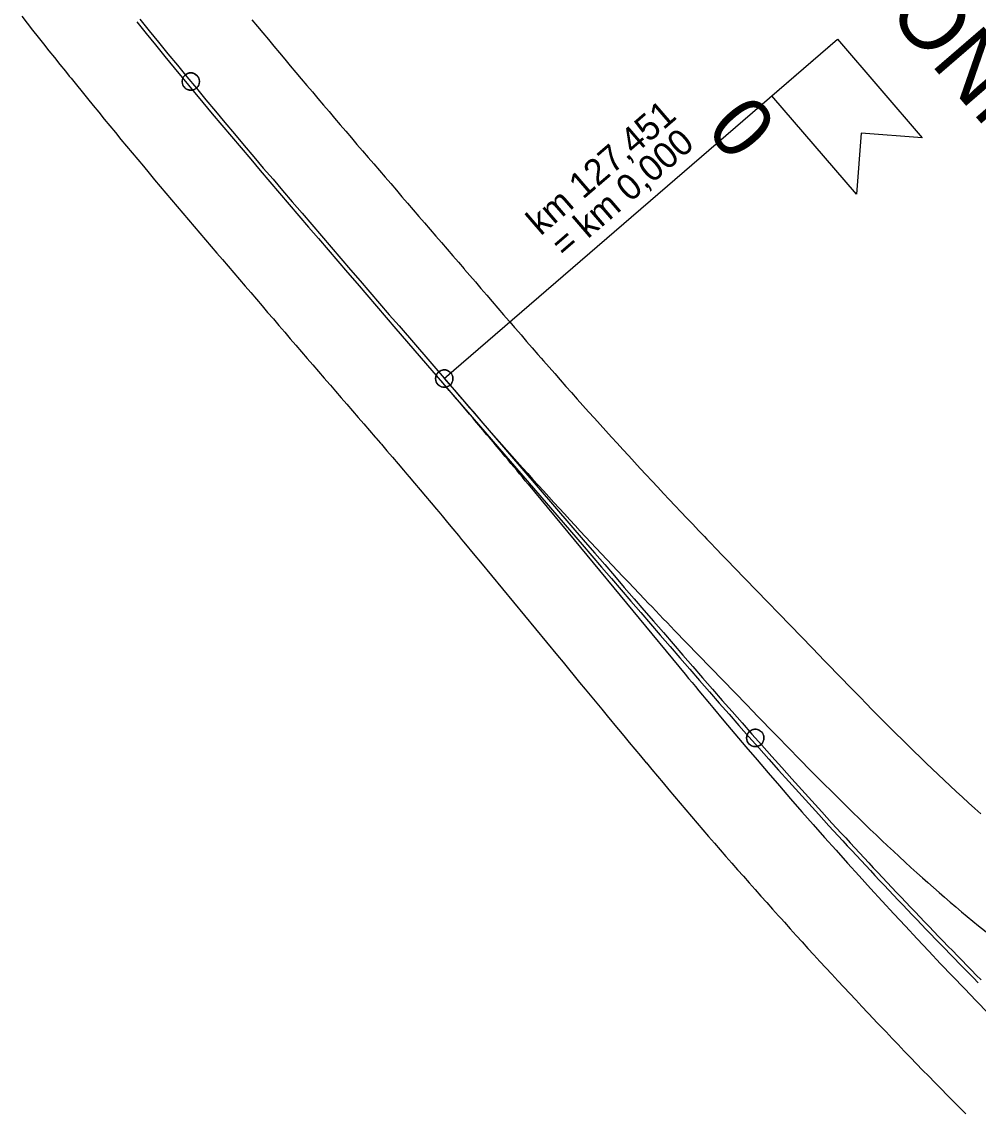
# Model space of a CAD drawing. Extents: x -670810 to -649614, y -1131928 to -1115069.
# Drawn here: x -669291 to -668186, y -1123186 to -1121929 of the extents above; entities that cross this region are included whole.
import ezdxf

# ---------------------------------------------------------------- set-up
doc = ezdxf.new("R2010")
doc.units = 0
for name, color, linetype in [('519 Var SK-4 Praporky stanic', 7, 'Continuous'), ('hranice_VRT_ZUR_Vysocina', 7, 'Continuous'), ('Situace - Osa koleje 2D', 7, 'Continuous'), ('Staničení - hlavní staničení + kolečka 1k', 7, 'Continuous')]:
    doc.layers.add(name, color=color, linetype=linetype)

# ---------------------------------------------------------------- blocks, each defined once
blk = doc.blocks.new('Sit10Kruh_104')
at = {"layer": 'Staničení - hlavní staničení + kolečka 1k'}
blk.add_lwpolyline([(10, 0), (10, 0.6), (9.9, 1.3), (9.8, 1.9), (9.7, 2.5), (9.5, 3.1), (9.3, 3.7), (9, 4.3), (8.8, 4.8), (8.4, 5.4), (8.1, 5.9), (7.7, 6.4), (7.3, 6.8), (6.8, 7.3), (6.4, 7.7), (5.9, 8.1), (5.4, 8.4), (4.8, 8.8), (4.3, 9), (3.7, 9.3), (3.1, 9.5), (2.5, 9.7), (1.9, 9.8), (1.3, 9.9), (0.6, 10), (0, 10), (-0.6, 10), (-1.3, 9.9), (-1.9, 9.8), (-2.5, 9.7), (-3.1, 9.5), (-3.7, 9.3), (-4.3, 9), (-4.8, 8.8), (-5.4, 8.4), (-5.9, 8.1), (-6.4, 7.7), (-6.8, 7.3), (-7.3, 6.8), (-7.7, 6.4), (-8.1, 5.9), (-8.4, 5.4), (-8.8, 4.8), (-9, 4.3), (-9.3, 3.7), (-9.5, 3.1), (-9.7, 2.5), (-9.8, 1.9), (-9.9, 1.3), (-10, 0.6), (-10, 0), (-10, -0.6), (-9.9, -1.3), (-9.8, -1.9), (-9.7, -2.5), (-9.5, -3.1), (-9.3, -3.7), (-9, -4.3), (-8.8, -4.8), (-8.4, -5.4), (-8.1, -5.9), (-7.7, -6.4), (-7.3, -6.8), (-6.8, -7.3), (-6.4, -7.7), (-5.9, -8.1), (-5.4, -8.4), (-4.8, -8.8), (-4.3, -9), (-3.7, -9.3), (-3.1, -9.5), (-2.5, -9.7), (-1.9, -9.8), (-1.3, -9.9), (-0.6, -10), (0, -10), (0.6, -10), (1.3, -9.9), (1.9, -9.8), (2.5, -9.7), (3.1, -9.5), (3.7, -9.3), (4.3, -9), (4.8, -8.8), (5.4, -8.4), (5.9, -8.1), (6.4, -7.7), (6.8, -7.3), (7.3, -6.8), (7.7, -6.4), (8.1, -5.9), (8.4, -5.4), (8.8, -4.8), (9, -4.3), (9.3, -3.7), (9.5, -3.1), (9.7, -2.5), (9.8, -1.9), (9.9, -1.3)], close=True, dxfattribs=at)
blk.add_circle((0, 0), 10, dxfattribs=at)
blk = doc.blocks.new('Sit10Kruh_105')
at = {"layer": 'Staničení - hlavní staničení + kolečka 1k'}
blk.add_lwpolyline([(10, 0), (10, 0.6), (9.9, 1.3), (9.8, 1.9), (9.7, 2.5), (9.5, 3.1), (9.3, 3.7), (9, 4.3), (8.8, 4.8), (8.4, 5.4), (8.1, 5.9), (7.7, 6.4), (7.3, 6.8), (6.8, 7.3), (6.4, 7.7), (5.9, 8.1), (5.4, 8.4), (4.8, 8.8), (4.3, 9), (3.7, 9.3), (3.1, 9.5), (2.5, 9.7), (1.9, 9.8), (1.3, 9.9), (0.6, 10), (0, 10), (-0.6, 10), (-1.3, 9.9), (-1.9, 9.8), (-2.5, 9.7), (-3.1, 9.5), (-3.7, 9.3), (-4.3, 9), (-4.8, 8.8), (-5.4, 8.4), (-5.9, 8.1), (-6.4, 7.7), (-6.8, 7.3), (-7.3, 6.8), (-7.7, 6.4), (-8.1, 5.9), (-8.4, 5.4), (-8.8, 4.8), (-9, 4.3), (-9.3, 3.7), (-9.5, 3.1), (-9.7, 2.5), (-9.8, 1.9), (-9.9, 1.3), (-10, 0.6), (-10, 0), (-10, -0.6), (-9.9, -1.3), (-9.8, -1.9), (-9.7, -2.5), (-9.5, -3.1), (-9.3, -3.7), (-9, -4.3), (-8.8, -4.8), (-8.4, -5.4), (-8.1, -5.9), (-7.7, -6.4), (-7.3, -6.8), (-6.8, -7.3), (-6.4, -7.7), (-5.9, -8.1), (-5.4, -8.4), (-4.8, -8.8), (-4.3, -9), (-3.7, -9.3), (-3.1, -9.5), (-2.5, -9.7), (-1.9, -9.8), (-1.3, -9.9), (-0.6, -10), (0, -10), (0.6, -10), (1.3, -9.9), (1.9, -9.8), (2.5, -9.7), (3.1, -9.5), (3.7, -9.3), (4.3, -9), (4.8, -8.8), (5.4, -8.4), (5.9, -8.1), (6.4, -7.7), (6.8, -7.3), (7.3, -6.8), (7.7, -6.4), (8.1, -5.9), (8.4, -5.4), (8.8, -4.8), (9, -4.3), (9.3, -3.7), (9.5, -3.1), (9.7, -2.5), (9.8, -1.9), (9.9, -1.3)], close=True, dxfattribs=at)
blk.add_circle((0, 0), 10, dxfattribs=at)
blk = doc.blocks.new('Sit10Kruh_167')
at = {"layer": 'Staničení - hlavní staničení + kolečka 1k'}
blk.add_lwpolyline([(10, 0), (10, 0.6), (9.9, 1.3), (9.8, 1.9), (9.7, 2.5), (9.5, 3.1), (9.3, 3.7), (9, 4.3), (8.8, 4.8), (8.4, 5.4), (8.1, 5.9), (7.7, 6.4), (7.3, 6.8), (6.8, 7.3), (6.4, 7.7), (5.9, 8.1), (5.4, 8.4), (4.8, 8.8), (4.3, 9), (3.7, 9.3), (3.1, 9.5), (2.5, 9.7), (1.9, 9.8), (1.3, 9.9), (0.6, 10), (0, 10), (-0.6, 10), (-1.3, 9.9), (-1.9, 9.8), (-2.5, 9.7), (-3.1, 9.5), (-3.7, 9.3), (-4.3, 9), (-4.8, 8.8), (-5.4, 8.4), (-5.9, 8.1), (-6.4, 7.7), (-6.8, 7.3), (-7.3, 6.8), (-7.7, 6.4), (-8.1, 5.9), (-8.4, 5.4), (-8.8, 4.8), (-9, 4.3), (-9.3, 3.7), (-9.5, 3.1), (-9.7, 2.5), (-9.8, 1.9), (-9.9, 1.3), (-10, 0.6), (-10, 0), (-10, -0.6), (-9.9, -1.3), (-9.8, -1.9), (-9.7, -2.5), (-9.5, -3.1), (-9.3, -3.7), (-9, -4.3), (-8.8, -4.8), (-8.4, -5.4), (-8.1, -5.9), (-7.7, -6.4), (-7.3, -6.8), (-6.8, -7.3), (-6.4, -7.7), (-5.9, -8.1), (-5.4, -8.4), (-4.8, -8.8), (-4.3, -9), (-3.7, -9.3), (-3.1, -9.5), (-2.5, -9.7), (-1.9, -9.8), (-1.3, -9.9), (-0.6, -10), (0, -10), (0.6, -10), (1.3, -9.9), (1.9, -9.8), (2.5, -9.7), (3.1, -9.5), (3.7, -9.3), (4.3, -9), (4.8, -8.8), (5.4, -8.4), (5.9, -8.1), (6.4, -7.7), (6.8, -7.3), (7.3, -6.8), (7.7, -6.4), (8.1, -5.9), (8.4, -5.4), (8.8, -4.8), (9, -4.3), (9.3, -3.7), (9.5, -3.1), (9.7, -2.5), (9.8, -1.9), (9.9, -1.3)], close=True, dxfattribs=at)
blk.add_circle((0, 0), 10, dxfattribs=at)
blk = doc.blocks.new('_U497')
at = {"layer": '519 Var SK-4 Praporky stanic'}
blk.add_line((-45.8, -299.9), (-45.8, 299.9), dxfattribs=at)
blk.add_lwpolyline([(-45.8, 299.9), (104.2, 299.9), (54.2, 249.9), (104.2, 199.9), (-45.8, 199.9)], close=True, dxfattribs=at)
for s, p in [('km 127,451', (-97.4, -108.5)), ('= km 0,000', (-59.2, -104))]:
    blk.add_text(s, height=30, rotation=90, dxfattribs=at).set_placement(p)
blk = doc.blocks.new('_U496')
at = {"layer": '519 Var SK-4 Praporky stanic'}
blk.add_blockref('_U497', (45.8, -87.5), dxfattribs=at)
blk.add_text('ODB ANTONÍNŮV DŮL', height=75, dxfattribs=at).set_placement((-432.7, 274.9))

msp = doc.modelspace()

# ---------------------------------------------------------------- linework, layer by layer
at = {"layer": 'hranice_VRT_ZUR_Vysocina'}
for points in [[(-669291.2, -1121922.8), (-669284.9, -1121930.7), (-669278.6, -1121938.7), (-669272.3, -1121946.7), (-669266, -1121954.6), (-669259.7, -1121962.5), (-669253.3, -1121970.5), (-669247, -1121978.4), (-669240.6, -1121986.3), (-669236.2, -1121991.8), (-669234.2, -1121994.2), (-669227.9, -1122002.1), (-669221.5, -1122010), (-669215.1, -1122017.9), (-669208.7, -1122025.7), (-669202.2, -1122033.6), (-669195.8, -1122041.4), (-669189.4, -1122049.3), (-669182.9, -1122057.1), (-669176.5, -1122064.9), (-669170, -1122072.7), (-669163.5, -1122080.5), (-669157.1, -1122088.3), (-669150.6, -1122096), (-669144.1, -1122103.8), (-669137.6, -1122111.5), (-669131.1, -1122119.3), (-669124.6, -1122127), (-669118, -1122134.7), (-669111.5, -1122142.4), (-669105, -1122150.1), (-669098.5, -1122157.8), (-669092, -1122165.5), (-669085.4, -1122173.2), (-669078.9, -1122180.9), (-669072.3, -1122188.5), (-669065.8, -1122196.2), (-669059.3, -1122203.8), (-669052.7, -1122211.4), (-669046.2, -1122219.1), (-669039.7, -1122226.7), (-669033.1, -1122234.3), (-669026.6, -1122241.9), (-669020, -1122249.5), (-669013.5, -1122257.1), (-669007, -1122264.7), (-669000.4, -1122272.3), (-668993.9, -1122279.9), (-668987.3, -1122287.5), (-668980.8, -1122295.1), (-668974.3, -1122302.6), (-668967.7, -1122310.2), (-668961.2, -1122317.8), (-668954.7, -1122325.4), (-668948.1, -1122332.9), (-668941.6, -1122340.5), (-668935.1, -1122348.1), (-668934.4, -1122348.8), (-668928.5, -1122355.7), (-668922, -1122363.2), (-668915.5, -1122370.8), (-668908.9, -1122378.4), (-668902.4, -1122386), (-668895.9, -1122393.5), (-668889.4, -1122401.1), (-668882.8, -1122408.7), (-668882.1, -1122409.5)], [(-669025.1, -1121926.8), (-669018.8, -1121934.4), (-669012.5, -1121942), (-669006.2, -1121949.6), (-668999.8, -1121957.2), (-668993.5, -1121964.8), (-668987.2, -1121972.3), (-668980.8, -1121979.9), (-668974.4, -1121987.5), (-668968.1, -1121995.1), (-668961.7, -1122002.6), (-668955.3, -1122010.2), (-668948.9, -1122017.8), (-668942.4, -1122025.3), (-668936, -1122032.9), (-668929.6, -1122040.5), (-668923.1, -1122048), (-668916.7, -1122055.6), (-668910.2, -1122063.1), (-668903.8, -1122070.7), (-668897.3, -1122078.2), (-668890.8, -1122085.8), (-668884.3, -1122093.3), (-668877.8, -1122100.9), (-668871.3, -1122108.5), (-668864.8, -1122116), (-668858.3, -1122123.6), (-668851.8, -1122131.1), (-668845.3, -1122138.7), (-668838.8, -1122146.3), (-668832.3, -1122153.8), (-668825.8, -1122161.4), (-668819.2, -1122169), (-668812.7, -1122176.5), (-668806.2, -1122184.1), (-668799.7, -1122191.7), (-668793.1, -1122199.3), (-668786.6, -1122206.8), (-668780.1, -1122214.4), (-668779.4, -1122215.1), (-668773.5, -1122222), (-668767, -1122229.5), (-668760.5, -1122237.1), (-668753.9, -1122244.7), (-668747.4, -1122252.3), (-668740.9, -1122259.8), (-668734.3, -1122267.4), (-668727.8, -1122275), (-668727.1, -1122275.8)], [(-668727.1, -1122275.8), (-668721.7, -1122282.1), (-668720.6, -1122283.3), (-668714.2, -1122290.8), (-668707.7, -1122298.3), (-668701.2, -1122305.7), (-668694.7, -1122313.2), (-668690.8, -1122317.6), (-668688.3, -1122320.5), (-668681.8, -1122328), (-668675.3, -1122335.3), (-668668.8, -1122342.7), (-668662.3, -1122350.1), (-668655.7, -1122357.4), (-668649.2, -1122364.8), (-668642.6, -1122372.1), (-668636.1, -1122379.4), (-668629.5, -1122386.8), (-668622.9, -1122394.1), (-668616.3, -1122401.4), (-668609.7, -1122408.6), (-668603.1, -1122415.9), (-668596.4, -1122423.2), (-668589.8, -1122430.4), (-668583.1, -1122437.6), (-668576.4, -1122444.9), (-668569.7, -1122452.1), (-668563, -1122459.3), (-668556.3, -1122466.5), (-668549.6, -1122473.7), (-668542.9, -1122480.8), (-668536.1, -1122488), (-668529.4, -1122495.1), (-668522.6, -1122502.3), (-668515.8, -1122509.4), (-668509, -1122516.5), (-668502.2, -1122523.6), (-668499.4, -1122526.6), (-668495.4, -1122530.7), (-668488.6, -1122537.8), (-668481.7, -1122545), (-668474.8, -1122552.1), (-668467.8, -1122559.3), (-668377.4, -1122652.6), (-668370.5, -1122659.8), (-668363.5, -1122667), (-668356.6, -1122674.1), (-668349.7, -1122681.2), (-668342.8, -1122688.3), (-668335.9, -1122695.4), (-668329, -1122702.5), (-668322.1, -1122709.5), (-668315.2, -1122716.5), (-668308.3, -1122723.5), (-668301.4, -1122730.5), (-668294.5, -1122737.4), (-668287.6, -1122744.3), (-668280.7, -1122751.2), (-668273.8, -1122758), (-668266.9, -1122764.8), (-668260, -1122771.6), (-668253, -1122778.4), (-668246.1, -1122785.1), (-668239.1, -1122791.7), (-668232.2, -1122798.4), (-668225.2, -1122805), (-668218.2, -1122811.5), (-668211.2, -1122818), (-668204.2, -1122824.5), (-668197.1, -1122830.9), (-668190, -1122837.4), (-668183, -1122843.6)], [(-668882.1, -1122409.5), (-668876.7, -1122415.8), (-668875.6, -1122417), (-668869.2, -1122424.5), (-668862.8, -1122432), (-668856.3, -1122439.5), (-668849.9, -1122447), (-668846.1, -1122451.5), (-668843.6, -1122454.5), (-668837.2, -1122462), (-668830.8, -1122469.5), (-668824.5, -1122477), (-668818.2, -1122484.5), (-668811.8, -1122492.1), (-668809.3, -1122495.1), (-668805.5, -1122499.6), (-668799.2, -1122507.2), (-668792.9, -1122514.8), (-668786.6, -1122522.5), (-668783, -1122526.8), (-668780.2, -1122530.1), (-668767.5, -1122545.5), (-668761.1, -1122553.2), (-668671.9, -1122661.1), (-668665.6, -1122668.8), (-668646.5, -1122692), (-668640.1, -1122699.7), (-668621, -1122722.8), (-668614.6, -1122730.5), (-668601.9, -1122745.9), (-668601.6, -1122746.2), (-668595.5, -1122753.6), (-668589.1, -1122761.4), (-668582.6, -1122769.1), (-668576.2, -1122776.9), (-668569.7, -1122784.7), (-668569.4, -1122785), (-668563.2, -1122792.5), (-668556.7, -1122800.3), (-668550.1, -1122808.1), (-668543.6, -1122815.9), (-668537, -1122823.6), (-668530.4, -1122831.4), (-668523.8, -1122839.1), (-668517.2, -1122846.8), (-668510.6, -1122854.6), (-668504, -1122862.3), (-668497.4, -1122870), (-668490.7, -1122877.6), (-668484, -1122885.3), (-668477.4, -1122893), (-668470.7, -1122900.6), (-668464, -1122908.3), (-668457.2, -1122915.9), (-668450.5, -1122923.5), (-668443.8, -1122931.1), (-668437, -1122938.7), (-668430.3, -1122946.3), (-668423.5, -1122953.9), (-668416.7, -1122961.4), (-668413.7, -1122964.8), (-668409.9, -1122969), (-668403.1, -1122976.5), (-668396.3, -1122984.1), (-668389.4, -1122991.6), (-668382.6, -1122999.1), (-668375.7, -1123006.6), (-668368.8, -1123014.1), (-668361.9, -1123021.5), (-668355, -1123029), (-668348.1, -1123036.5), (-668341.2, -1123043.9), (-668334.2, -1123051.3), (-668327.3, -1123058.7), (-668320.3, -1123066.1), (-668313.4, -1123073.5), (-668306.4, -1123080.9), (-668303.3, -1123084.2), (-668299.4, -1123088.3), (-668292.4, -1123095.6), (-668285.3, -1123103), (-668278.3, -1123110.3), (-668271.3, -1123117.7), (-668264.2, -1123125), (-668257.1, -1123132.3), (-668250.1, -1123139.6), (-668243, -1123146.8), (-668235.9, -1123154.1), (-668228.7, -1123161.4), (-668221.6, -1123168.6), (-668214.5, -1123175.8), (-668207.3, -1123183.1), (-668200.1, -1123190.3)]]:
    msp.add_lwpolyline(points, dxfattribs=at)
at = {"layer": 'Situace - Osa koleje 2D'}
for p, q in [((-668858.7, -1122283.6), (-668643.6, -1122532.9)), ((-668855.2, -1122280.4), (-668640, -1122529.9)), ((-668802.9, -1122341.1), (-668797.4, -1122347.4)), ((-668806.4, -1122344.2), (-668801, -1122350.5)), ((-668705.9, -1122463.1), (-668524.6, -1122682.5)), ((-668536.8, -1122631.9), (-668453.3, -1122718))]:
    msp.add_line(p, q, dxfattribs=at)
for points in [[(-669154.7, -1121926.1), (-669143.9, -1121939.5), (-669133, -1121952.8), (-669122.2, -1121966.1), (-669111.3, -1121979.4), (-669100.3, -1121992.7), (-669089.4, -1122005.9), (-669078.4, -1122019.1), (-669067.4, -1122032.3), (-669056.3, -1122045.5), (-669045.3, -1122058.6), (-669034.2, -1122071.8), (-669023.1, -1122084.9), (-669012, -1122098), (-669000.8, -1122111), (-668989.7, -1122124.1), (-668978.5, -1122137.2), (-668967.3, -1122150.2), (-668956.1, -1122163.3), (-668944.9, -1122176.3), (-668933.7, -1122189.3), (-668922.5, -1122202.3), (-668911.3, -1122215.4), (-668900, -1122228.4), (-668888.8, -1122241.4), (-668877.6, -1122254.4), (-668866.4, -1122267.4), (-668855.2, -1122280.4)], [(-669158.3, -1121929.1), (-669147.5, -1121942.5), (-669136.6, -1121955.8), (-669125.8, -1121969.1), (-669114.9, -1121982.4), (-669103.9, -1121995.7), (-669093, -1122008.9), (-669082, -1122022.2), (-669071, -1122035.3), (-669059.9, -1122048.5), (-669048.8, -1122061.7), (-669037.8, -1122074.8), (-669026.6, -1122087.9), (-669015.5, -1122101), (-669004.4, -1122114.1), (-668993.2, -1122127.2), (-668982, -1122140.3), (-668970.8, -1122153.3), (-668959.7, -1122166.4), (-668948.4, -1122179.4), (-668937.2, -1122192.4), (-668926, -1122205.5), (-668914.8, -1122218.5), (-668903.6, -1122231.5), (-668892.3, -1122244.5), (-668881.1, -1122257.5), (-668869.9, -1122270.6), (-668858.7, -1122283.6)], [(-668640, -1122529.9), (-668628.8, -1122542.9), (-668617.5, -1122556), (-668606.2, -1122569.1), (-668594.9, -1122582.2), (-668583.6, -1122595.3), (-668572.3, -1122608.4), (-668561, -1122621.4), (-668549.7, -1122634.5), (-668538.4, -1122647.6), (-668527.1, -1122660.6), (-668515.7, -1122673.7), (-668504.4, -1122686.7), (-668493, -1122699.7), (-668481.6, -1122712.7), (-668470.3, -1122725.7), (-668458.8, -1122738.7), (-668447.4, -1122751.6), (-668435.9, -1122764.6), (-668424.4, -1122777.5), (-668412.9, -1122790.3), (-668401.4, -1122803.2), (-668389.8, -1122816), (-668378.2, -1122828.8), (-668366.6, -1122841.6), (-668354.9, -1122854.4)], [(-668643.6, -1122532.9), (-668632.4, -1122546), (-668621.1, -1122559.1), (-668609.8, -1122572.1), (-668598.5, -1122585.2), (-668587.2, -1122598.3), (-668575.9, -1122611.4), (-668564.6, -1122624.5), (-668553.3, -1122637.6), (-668542, -1122650.6), (-668530.6, -1122663.7), (-668519.3, -1122676.7), (-668508, -1122689.8), (-668496.6, -1122702.8), (-668485.2, -1122715.8), (-668473.8, -1122728.8), (-668462.4, -1122741.8), (-668450.9, -1122754.7), (-668439.5, -1122767.7), (-668428, -1122780.6), (-668416.5, -1122793.5), (-668404.9, -1122806.3), (-668393.3, -1122819.1), (-668381.7, -1122832), (-668370.1, -1122844.7), (-668358.4, -1122857.5)], [(-668571.5, -1122595.9), (-668567.2, -1122600.4), (-668562.8, -1122604.9), (-668558.5, -1122609.4), (-668554.1, -1122613.9), (-668549.8, -1122618.4), (-668545.4, -1122622.9), (-668541.1, -1122627.4), (-668536.8, -1122631.9)], [(-668524.6, -1122682.5), (-668520.6, -1122687.3), (-668516.6, -1122692.1), (-668512.6, -1122696.9), (-668508.6, -1122701.8), (-668504.6, -1122706.6), (-668500.6, -1122711.4), (-668496.6, -1122716.2), (-668492.6, -1122721)], [(-668453.3, -1122718), (-668446.9, -1122724.7), (-668440.5, -1122731.3), (-668434.1, -1122737.9), (-668427.7, -1122744.5), (-668421.3, -1122751.1), (-668414.8, -1122757.7), (-668408.4, -1122764.3), (-668402, -1122770.8), (-668395.5, -1122777.4), (-668389.1, -1122784), (-668382.6, -1122790.5), (-668376.2, -1122797.1), (-668369.7, -1122803.6), (-668363.2, -1122810.1), (-668356.7, -1122816.6), (-668350.2, -1122823.1), (-668343.6, -1122829.6), (-668337.1, -1122836), (-668330.5, -1122842.5), (-668323.9, -1122848.9), (-668317.3, -1122855.3), (-668310.7, -1122861.7), (-668304, -1122868), (-668297.4, -1122874.4), (-668290.7, -1122880.7), (-668283.9, -1122887), (-668277.2, -1122893.2), (-668270.4, -1122899.4), (-668263.6, -1122905.6), (-668256.8, -1122911.8)]]:
    msp.add_lwpolyline(points, dxfattribs=at)
for centre, radius, start, end in [((-674492.5, -1127259.3), 7516, 40.41382, 40.77709), ((-663106, -1117438.7), 7515.8, 220.77709, 221.14041), ((-673414.4, -1126341.3), 6100, 39.86846, 40.41382), ((-664172.3, -1118370.2), 6100, 221.14041, 223.84752), ((-674976.1, -1127645.6), 8134.7, 39.57494, 39.86846), ((-663806.8, -1118815.5), 6100, 219.80976, 225.76422), ((-663197.7, -1118121.2), 7004.7, 222.54449, 224.5922), ((-663197.7, -1118121.2), 7000, 222.54508, 224.5916), ((-666919.5, -1121424.7), 2000, 228.0357, 235.88)]:
    msp.add_arc(centre, radius, start, end, dxfattribs=at)

# ---------------------------------------------------------------- block references
at = {"layer": '519 Var SK-4 Praporky stanic', "rotation": -49.222906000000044}
msp.add_blockref('_U496', (-668509.5, -1122088.1), dxfattribs=at)
at = {"layer": 'Staničení - hlavní staničení + kolečka 1k'}
for name, p, rotation in [('Sit10Kruh_104', (-669095.8, -1121998.1), -50.387899), ('Sit10Kruh_167', (-668802.9, -1122341.1), -49.222906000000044), ('Sit10Kruh_105', (-668443.5, -1122756.1), -48.45203500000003)]:
    msp.add_blockref(name, p, dxfattribs=dict(at, rotation=rotation))

# ---------------------------------------------------------------- texts
msp.add_text('0', height=70, rotation=310.7771, dxfattribs=at).set_placement((-668502.3, -1122054.2))

doc.saveas('drawing.dxf')
